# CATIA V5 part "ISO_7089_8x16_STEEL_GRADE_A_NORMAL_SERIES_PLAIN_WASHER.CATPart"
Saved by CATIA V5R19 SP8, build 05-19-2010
Part number: ISO 7089 WASHER 8x16 STEEL GRADE A PLAIN NORMAL SERIES
Nomenclature: 33
Publications: "Mating Face", "Axis"
Bounding box of the stored display mesh (mm): x 0 to 1.6, y -8 to 8, z -8 to 8
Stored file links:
  C:\Users\rphgr\Desktop\0_Tapis_TC520B_vitesse\ISO_7089_8x16_STEEL_GRADE_A_NORMAL_SERIES_PLAIN_WASHER.CATPart
  D:\Programmes\DassaultSysteme\win_b64\startup\components\MechanicalStandardParts\ISO_Standards\Design_Tables\ISO_7089_PLAIN_WASHER_GRADE_A_NORMAL_SERIES.txt
  C:\Program Files\Dassault Systemes\B19\win_b64\startup\components\MechanicalStandardParts\ISO_Standards\Design_Tables\ISO_7089_PLAIN_WASHER_GRADE_A_NORMAL_SERIES.txt
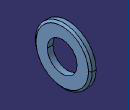
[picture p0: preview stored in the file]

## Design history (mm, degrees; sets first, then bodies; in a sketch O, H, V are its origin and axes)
Parameters
  d1_inside_dia = 8.4 mm
  d2_outside_dia = 16 mm
  h_thick = 1.6 mm
  Nominal_dia = 8 mm
Body1 "PartBody" (main body)
  Sketch1 on yz-plane, origin (0, 0, 0), H (0, 1, 0), V (0, 0, 1)
    circle A1 centre (0, 0) radius 8
    circle A2 centre (0, 0) radius 4.2
    radius A1 = 8 {= d2_outside_dia /2}
    radius A2 = 4.2 {= d1_inside_dia /2}
  Pad1: profile Sketch1, direction (1, 0, 0), length 1.6 {= h_thick}
  Chamfer1: length 0.6 {= 0.375*h_thick}, angle 37.5, on edge [face of Pad1 | face of Pad1]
